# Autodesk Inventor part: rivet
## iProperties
Author: chr
Created: 2001-06
Part Number: rivet
Material: Par défaut
Document SubType Name: Modélisation
Designer: chr
Control State: 0
Master: False
Checked Out: False
PropertySet Name: Design Tracking Control
Shininess: 20.0
PropertySet Name: _Private Model Information
Length Units: 11269
Angle Units: 11286
Time Units: 11279
Mass Units: 11290
Length Display Precision: 3
Angle Display Precision: 2
Compacted: False
Density: 0.0
Volumn: 0.0
Area: 0.0
PropertySet Name: Model Information
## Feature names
1. Révolution1 [Revolution]
